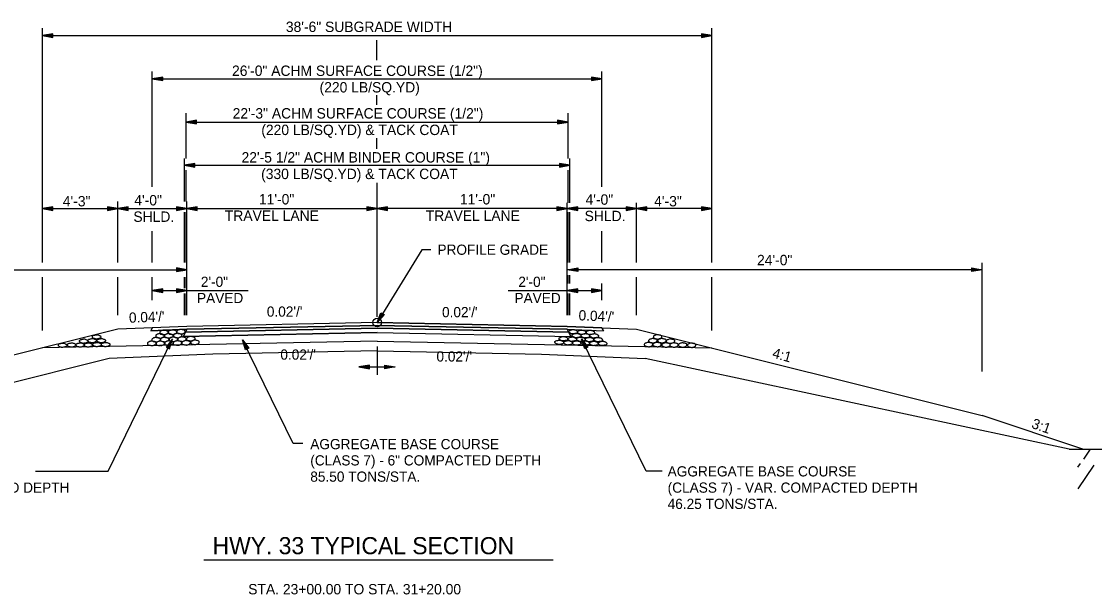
# Model space of a CAD drawing. Extents: x 1461846 to 1462006, y 1686171 to 1686805.
# Drawn here: x 1461905.5 to 1461967.5, y 1686172.9 to 1686206 of the extents above; entities that cross this region are included whole.
import ezdxf

# ---------------------------------------------------------------- set-up
doc = ezdxf.new("R2010")
doc.units = 0
for name, color, linetype in [('1', 7, 'Continuous'), ('10', 7, 'Continuous'), ('12', 7, 'Continuous'), ('19', 7, 'Continuous'), ('42', 7, 'Continuous'), ('Level 1', 7, 'Continuous'), ('Level 7', 7, 'Continuous'), ('Level 9', 7, 'Continuous')]:
    doc.layers.add(name, color=color, linetype=linetype)

# ---------------------------------------------------------------- blocks, each defined once
blk = doc.blocks.new('ROCKS')
at = {"layer": '1'}
blk.add_spline([(0.013, 0.06), (0.053, 0.053), (0.107, 0.033), (0.133, 0.013), (0.133, -0.007), (0.12, -0.033), (0.107, -0.04), (0.073, -0.053), (0.033, -0.067), (0.013, -0.067), (-0.02, -0.06), (-0.06, -0.053), (-0.087, -0.047), (-0.113, -0.02), (-0.113, -0.007), (-0.107, 0.02), (-0.087, 0.033), (-0.067, 0.047), (-0.033, 0.053), (-0.02, 0.06), (0.013, 0.06)], degree=3, dxfattribs=at)
blk = doc.blocks.new('4TO1 ABC')
at = {"layer": '1', "xscale": 0.1312491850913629, "yscale": 0.1312491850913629, "rotation": 180}
for p in [(0.00175, -0.00875), (-0.03325, -0.0385), (-0.016625, -0.023625), (0, -0.0385), (0.018375, -0.023625), (0.034125, -0.04025), (0.051625, -0.025375), (0.06475, -0.04025), (0.098, -0.04025), (0.133, -0.041125)]:
    blk.add_blockref('ROCKS', p, dxfattribs=at)

msp = doc.modelspace()

# ---------------------------------------------------------------- linework, layer by layer
at = {"layer": '10'}
msp.add_line((1461916.031, 1686174.906), (1461936.226, 1686174.906), dxfattribs=at)
at = {"layer": '19'}
for p, q in [((1461907.286, 1686205.314), (1461906.686, 1686205.209)), ((1461906.686, 1686205.209), (1461945.406, 1686205.209)), ((1461906.686, 1686205.209), (1461907.286, 1686205.104)), ((1461907.286, 1686205.259), (1461906.846, 1686205.224)), ((1461906.846, 1686205.194), (1461907.286, 1686205.154)), ((1461907.286, 1686205.104), (1461907.286, 1686205.314)), ((1461926.035, 1686203.793), (1461926.035, 1686204.941)), ((1461944.806, 1686205.314), (1461944.806, 1686205.104)), ((1461945.406, 1686205.209), (1461944.806, 1686205.314)), ((1461945.246, 1686205.224), (1461944.806, 1686205.259)), ((1461944.806, 1686205.104), (1461945.406, 1686205.209)), ((1461944.806, 1686205.154), (1461945.246, 1686205.194)), ((1461913.646, 1686202.814), (1461913.046, 1686202.709)), ((1461913.046, 1686202.709), (1461939.046, 1686202.709)), ((1461913.046, 1686202.709), (1461913.646, 1686202.604)), ((1461913.646, 1686202.759), (1461913.206, 1686202.724)), ((1461913.206, 1686202.694), (1461913.646, 1686202.654)), ((1461913.646, 1686202.604), (1461913.646, 1686202.814)), ((1461938.446, 1686202.814), (1461938.446, 1686202.604)), ((1461939.046, 1686202.709), (1461938.446, 1686202.814)), ((1461938.886, 1686202.724), (1461938.446, 1686202.759)), ((1461938.446, 1686202.604), (1461939.046, 1686202.709)), ((1461938.446, 1686202.654), (1461938.886, 1686202.694)), ((1461926.035, 1686201.209), (1461926.035, 1686201.758)), ((1461915.604, 1686200.314), (1461915.004, 1686200.209)), ((1461915.004, 1686200.209), (1461937.088, 1686200.209)), ((1461915.004, 1686200.209), (1461915.604, 1686200.104)), ((1461915.604, 1686200.259), (1461915.164, 1686200.224)), ((1461915.164, 1686200.194), (1461915.604, 1686200.154)), ((1461915.604, 1686200.104), (1461915.604, 1686200.314)), ((1461936.488, 1686200.314), (1461936.488, 1686200.104)), ((1461937.088, 1686200.209), (1461936.488, 1686200.314)), ((1461936.928, 1686200.224), (1461936.488, 1686200.259)), ((1461936.488, 1686200.104), (1461937.088, 1686200.209)), ((1461936.488, 1686200.154), (1461936.928, 1686200.194)), ((1461926.035, 1686198.657), (1461926.035, 1686199.284)), ((1461915.499, 1686197.814), (1461914.899, 1686197.709)), ((1461914.899, 1686197.709), (1461937.193, 1686197.709)), ((1461914.899, 1686197.709), (1461915.499, 1686197.604)), ((1461915.499, 1686197.759), (1461915.059, 1686197.724)), ((1461915.059, 1686197.694), (1461915.499, 1686197.654)), ((1461915.499, 1686197.604), (1461915.499, 1686197.814)), ((1461936.593, 1686197.814), (1461936.593, 1686197.604)), ((1461937.193, 1686197.709), (1461936.593, 1686197.814)), ((1461937.033, 1686197.724), (1461936.593, 1686197.759)), ((1461936.593, 1686197.604), (1461937.193, 1686197.709)), ((1461936.593, 1686197.654), (1461937.033, 1686197.694)), ((1461907.286, 1686195.314), (1461906.686, 1686195.209)), ((1461906.686, 1686195.209), (1461907.286, 1686195.104)), ((1461907.286, 1686195.259), (1461906.846, 1686195.224)), ((1461906.846, 1686195.194), (1461907.286, 1686195.154)), ((1461907.286, 1686195.104), (1461907.286, 1686195.314)), ((1461910.446, 1686195.314), (1461910.446, 1686195.104)), ((1461911.046, 1686195.209), (1461910.446, 1686195.314)), ((1461910.886, 1686195.224), (1461910.446, 1686195.259)), ((1461910.446, 1686195.104), (1461911.046, 1686195.209)), ((1461910.446, 1686195.154), (1461910.886, 1686195.194)), ((1461911.646, 1686195.314), (1461911.046, 1686195.209)), ((1461911.046, 1686195.209), (1461911.646, 1686195.104)), ((1461911.646, 1686195.259), (1461911.206, 1686195.224)), ((1461911.206, 1686195.194), (1461911.646, 1686195.154)), ((1461911.646, 1686195.104), (1461911.646, 1686195.314)), ((1461914.446, 1686195.314), (1461914.446, 1686195.104)), ((1461915.046, 1686195.209), (1461914.446, 1686195.314)), ((1461914.886, 1686195.224), (1461914.446, 1686195.259)), ((1461914.446, 1686195.104), (1461915.046, 1686195.209)), ((1461914.446, 1686195.154), (1461914.886, 1686195.194)), ((1461915.646, 1686195.314), (1461915.046, 1686195.209)), ((1461915.046, 1686195.209), (1461915.646, 1686195.104)), ((1461915.646, 1686195.259), (1461915.206, 1686195.224)), ((1461915.206, 1686195.194), (1461915.646, 1686195.154)), ((1461915.646, 1686195.104), (1461915.646, 1686195.314)), ((1461925.446, 1686195.314), (1461925.446, 1686195.104)), ((1461926.046, 1686195.209), (1461925.446, 1686195.314)), ((1461925.886, 1686195.224), (1461925.446, 1686195.259)), ((1461925.446, 1686195.104), (1461926.046, 1686195.209)), ((1461925.446, 1686195.154), (1461925.886, 1686195.194)), ((1461926.646, 1686195.314), (1461926.046, 1686195.209)), ((1461926.046, 1686195.209), (1461926.646, 1686195.104)), ((1461926.646, 1686195.259), (1461926.206, 1686195.224)), ((1461926.206, 1686195.194), (1461926.646, 1686195.154)), ((1461926.646, 1686195.104), (1461926.646, 1686195.314)), ((1461936.446, 1686195.314), (1461936.446, 1686195.104)), ((1461937.046, 1686195.209), (1461936.446, 1686195.314)), ((1461936.886, 1686195.224), (1461936.446, 1686195.259)), ((1461936.446, 1686195.104), (1461937.046, 1686195.209)), ((1461936.446, 1686195.154), (1461936.886, 1686195.194)), ((1461937.646, 1686195.314), (1461937.046, 1686195.209)), ((1461937.046, 1686195.209), (1461937.646, 1686195.104)), ((1461937.646, 1686195.259), (1461937.206, 1686195.224)), ((1461937.206, 1686195.194), (1461937.646, 1686195.154)), ((1461937.646, 1686195.104), (1461937.646, 1686195.314)), ((1461940.446, 1686195.314), (1461940.446, 1686195.104)), ((1461941.046, 1686195.209), (1461940.446, 1686195.314)), ((1461940.886, 1686195.224), (1461940.446, 1686195.259)), ((1461940.446, 1686195.104), (1461941.046, 1686195.209)), ((1461940.446, 1686195.154), (1461940.886, 1686195.194)), ((1461941.646, 1686195.314), (1461941.046, 1686195.209)), ((1461941.046, 1686195.209), (1461941.646, 1686195.104)), ((1461941.646, 1686195.259), (1461941.206, 1686195.224)), ((1461941.206, 1686195.194), (1461941.646, 1686195.154)), ((1461941.646, 1686195.104), (1461941.646, 1686195.314)), ((1461944.806, 1686195.314), (1461944.806, 1686195.104)), ((1461945.406, 1686195.209), (1461944.806, 1686195.314)), ((1461945.246, 1686195.224), (1461944.806, 1686195.259)), ((1461944.806, 1686195.104), (1461945.406, 1686195.209)), ((1461944.806, 1686195.154), (1461945.246, 1686195.194)), ((1461914.446, 1686191.774), (1461914.446, 1686191.564)), ((1461915.046, 1686191.669), (1461914.446, 1686191.774)), ((1461914.886, 1686191.684), (1461914.446, 1686191.719)), ((1461937.046, 1686191.669), (1461937.646, 1686191.774)), ((1461937.206, 1686191.684), (1461937.646, 1686191.719)), ((1461937.646, 1686191.774), (1461937.646, 1686191.564)), ((1461960.446, 1686191.564), (1461960.446, 1686191.774)), ((1461960.446, 1686191.774), (1461961.046, 1686191.669)), ((1461960.446, 1686191.719), (1461960.886, 1686191.684)), ((1461914.446, 1686191.564), (1461915.046, 1686191.669)), ((1461914.446, 1686191.614), (1461914.886, 1686191.654)), ((1461937.646, 1686191.564), (1461937.046, 1686191.669)), ((1461937.646, 1686191.614), (1461937.206, 1686191.654)), ((1461961.046, 1686191.669), (1461960.446, 1686191.564)), ((1461960.886, 1686191.654), (1461960.446, 1686191.614)), ((1461913.646, 1686190.574), (1461913.046, 1686190.469)), ((1461913.046, 1686190.469), (1461918.583, 1686190.469)), ((1461913.046, 1686190.469), (1461913.646, 1686190.364)), ((1461913.646, 1686190.519), (1461913.206, 1686190.484)), ((1461913.206, 1686190.454), (1461913.646, 1686190.414)), ((1461913.646, 1686190.364), (1461913.646, 1686190.574)), ((1461914.446, 1686190.574), (1461914.446, 1686190.364)), ((1461915.046, 1686190.469), (1461914.446, 1686190.574)), ((1461914.886, 1686190.484), (1461914.446, 1686190.519)), ((1461914.446, 1686190.364), (1461915.046, 1686190.469)), ((1461914.446, 1686190.414), (1461914.886, 1686190.454)), ((1461933.62, 1686190.469), (1461939.046, 1686190.469)), ((1461937.646, 1686190.574), (1461937.046, 1686190.469)), ((1461937.046, 1686190.469), (1461937.646, 1686190.364)), ((1461937.646, 1686190.519), (1461937.206, 1686190.484)), ((1461937.206, 1686190.454), (1461937.646, 1686190.414)), ((1461937.646, 1686190.364), (1461937.646, 1686190.574)), ((1461938.446, 1686190.574), (1461938.446, 1686190.364)), ((1461939.046, 1686190.469), (1461938.446, 1686190.574)), ((1461938.886, 1686190.484), (1461938.446, 1686190.519)), ((1461938.446, 1686190.364), (1461939.046, 1686190.469)), ((1461938.446, 1686190.414), (1461938.886, 1686190.454)), ((1461926.046, 1686188.619), (1461915.046, 1686188.399)), ((1461926.046, 1686188.619), (1461915.046, 1686188.399)), ((1461926.046, 1686188.619), (1461926.269, 1686189.186)), ((1461926.447, 1686189.076), (1461926.046, 1686188.619)), ((1461926.046, 1686188.619), (1461937.046, 1686188.399)), ((1461937.046, 1686188.399), (1461926.046, 1686188.619)), ((1461926.12, 1686188.76), (1461926.313, 1686189.154)), ((1461926.406, 1686189.098), (1461926.143, 1686188.749)), ((1461926.269, 1686189.186), (1461926.447, 1686189.076)), ((1461911.046, 1686188.239), (1461891.046, 1686183.237)), ((1461915.046, 1686188.399), (1461911.046, 1686188.239)), ((1461913.046, 1686188.319), (1461912.961, 1686188.149)), ((1461913.046, 1686188.319), (1461912.961, 1686188.149)), ((1461915.046, 1686188.233), (1461912.961, 1686188.149)), ((1461912.961, 1686188.149), (1461915.046, 1686188.233)), ((1461915.046, 1686188.399), (1461913.046, 1686188.319)), ((1461914.962, 1686188.064), (1461914.835, 1686187.812)), ((1461914.962, 1686188.064), (1461914.835, 1686187.812)), ((1461926.046, 1686188.036), (1461914.835, 1686187.812)), ((1461914.835, 1686187.812), (1461926.046, 1686188.036)), ((1461926.046, 1686188.286), (1461914.962, 1686188.064)), ((1461914.962, 1686188.064), (1461926.046, 1686188.286)), ((1461926.046, 1686188.286), (1461914.962, 1686188.064)), ((1461915.046, 1686188.233), (1461914.962, 1686188.064)), ((1461915.046, 1686188.233), (1461914.962, 1686188.064)), ((1461926.046, 1686188.453), (1461915.046, 1686188.233)), ((1461915.046, 1686188.233), (1461926.046, 1686188.453)), ((1461926.046, 1686188.453), (1461915.046, 1686188.233)), ((1461926.046, 1686188.453), (1461937.046, 1686188.233)), ((1461926.046, 1686188.453), (1461937.046, 1686188.233)), ((1461937.046, 1686188.233), (1461926.046, 1686188.453)), ((1461926.046, 1686188.286), (1461937.13, 1686188.064)), ((1461926.046, 1686188.286), (1461937.13, 1686188.064)), ((1461937.13, 1686188.064), (1461926.046, 1686188.286)), ((1461926.046, 1686188.036), (1461937.256, 1686187.812)), ((1461926.046, 1686188.036), (1461937.256, 1686187.812)), ((1461937.046, 1686188.399), (1461941.046, 1686188.239)), ((1461939.046, 1686188.319), (1461937.046, 1686188.399)), ((1461937.046, 1686188.233), (1461939.131, 1686188.149)), ((1461937.046, 1686188.233), (1461937.13, 1686188.064)), ((1461937.046, 1686188.233), (1461939.131, 1686188.149)), ((1461937.13, 1686188.064), (1461937.046, 1686188.233)), ((1461937.13, 1686188.064), (1461937.256, 1686187.812)), ((1461937.256, 1686187.812), (1461937.13, 1686188.064)), ((1461939.046, 1686188.319), (1461939.131, 1686188.149)), ((1461939.131, 1686188.149), (1461939.046, 1686188.319)), ((1461941.046, 1686188.239), (1461961.046, 1686183.237)), ((1461926.046, 1686187.536), (1461906.686, 1686187.149)), ((1461910.487, 1686180.024), (1461914.215, 1686187.683)), ((1461914.215, 1686187.683), (1461913.852, 1686187.194)), ((1461914.133, 1686187.546), (1461913.901, 1686187.173)), ((1461913.995, 1686187.124), (1461914.158, 1686187.533)), ((1461914.039, 1686187.101), (1461914.215, 1686187.683)), ((1461921.185, 1686181.617), (1461918.264, 1686187.618)), ((1461918.44, 1686187.037), (1461918.264, 1686187.618)), ((1461918.264, 1686187.618), (1461918.627, 1686187.13)), ((1461918.484, 1686187.06), (1461918.321, 1686187.469)), ((1461918.346, 1686187.482), (1461918.579, 1686187.109)), ((1461926.046, 1686187.536), (1461945.406, 1686187.149)), ((1461941.604, 1686180.024), (1461937.876, 1686187.683)), ((1461938.053, 1686187.101), (1461937.876, 1686187.683)), ((1461937.876, 1686187.683), (1461938.24, 1686187.194)), ((1461938.097, 1686187.124), (1461937.934, 1686187.533)), ((1461937.959, 1686187.546), (1461938.191, 1686187.173)), ((1461916.546, 1686186.787), (1461910.546, 1686186.547)), ((1461913.852, 1686187.194), (1461914.039, 1686187.101)), ((1461926.046, 1686186.977), (1461916.546, 1686186.787)), ((1461918.627, 1686187.13), (1461918.44, 1686187.037)), ((1461926.046, 1686186.977), (1461935.546, 1686186.787)), ((1461935.546, 1686186.787), (1461941.546, 1686186.547)), ((1461938.24, 1686187.194), (1461938.053, 1686187.101)), ((1461910.546, 1686186.547), (1461903.549, 1686184.797)), ((1461966.072, 1686181.3), (1461941.546, 1686186.547)), ((1461966.857, 1686181.3), (1461961.046, 1686183.237)), ((1461921.755, 1686181.617), (1461921.185, 1686181.617)), ((1461966.072, 1686181.3), (1461979.182, 1686181.3)), ((1461966.915, 1686180.717), (1461967.306, 1686181.3)), ((1461906.289, 1686180.024), (1461910.487, 1686180.024)), ((1461942.524, 1686180.024), (1461941.604, 1686180.024)), ((1461966.575, 1686180.249), (1461966.729, 1686180.475)), ((1461966.597, 1686179), (1461967.524, 1686180.383))]:
    msp.add_line(p, q, dxfattribs=at)
msp.add_lwpolyline([(1461929.146, 1686192.818), (1461928.629, 1686192.818), (1461926.046, 1686188.619)], dxfattribs=at)
msp.add_circle((1461926.051, 1686188.617), 0.25, dxfattribs=at)
at = {"layer": '42'}
for p, q in [((1461926.046, 1686187.234), (1461926.046, 1686185.602)), ((1461925.598, 1686186.159), (1461924.998, 1686186.054)), ((1461925.598, 1686186.104), (1461925.158, 1686186.069)), ((1461925.598, 1686185.949), (1461925.598, 1686186.159)), ((1461926.493, 1686185.949), (1461926.493, 1686186.159)), ((1461926.493, 1686186.159), (1461927.093, 1686186.054)), ((1461926.493, 1686186.104), (1461926.933, 1686186.069)), ((1461924.998, 1686186.054), (1461925.598, 1686185.949)), ((1461924.998, 1686186.054), (1461927.093, 1686186.054)), ((1461925.158, 1686186.039), (1461925.598, 1686185.999)), ((1461927.093, 1686186.054), (1461926.493, 1686185.949)), ((1461926.933, 1686186.039), (1461926.493, 1686185.999))]:
    msp.add_line(p, q, dxfattribs=at)
at = {"layer": 'Level 7'}
msp.add_line((1461926.046, 1686188.94), (1461926.046, 1686196.705), dxfattribs=at)
at = {"layer": 'Level 9'}
for p, q in [((1461906.686, 1686192.097), (1461906.686, 1686205.636)), ((1461945.406, 1686192.097), (1461945.406, 1686205.636)), ((1461913.046, 1686196.466), (1461913.046, 1686203.136)), ((1461939.046, 1686196.466), (1461939.046, 1686203.136)), ((1461915.004, 1686198.098), (1461915.004, 1686200.715)), ((1461937.088, 1686198.098), (1461937.088, 1686200.715)), ((1461914.899, 1686195.612), (1461914.899, 1686198.098)), ((1461937.193, 1686195.541), (1461937.193, 1686198.098)), ((1461915.004, 1686195.612), (1461915.004, 1686197.427)), ((1461937.088, 1686195.541), (1461937.088, 1686197.427)), ((1461911.046, 1686192.097), (1461911.046, 1686195.612)), ((1461915.046, 1686189.045), (1461915.046, 1686195.612)), ((1461937.046, 1686189.045), (1461937.046, 1686195.541)), ((1461941.046, 1686192.097), (1461941.046, 1686195.541)), ((1461906.686, 1686195.209), (1461915.046, 1686195.209)), ((1461914.899, 1686192.097), (1461914.899, 1686194.994)), ((1461915.004, 1686192.097), (1461915.004, 1686194.994)), ((1461915.046, 1686195.209), (1461926.046, 1686195.209)), ((1461937.046, 1686195.209), (1461926.046, 1686195.209)), ((1461945.406, 1686195.209), (1461937.046, 1686195.209)), ((1461937.088, 1686192.097), (1461937.088, 1686194.994)), ((1461937.193, 1686192.097), (1461937.193, 1686194.994)), ((1461913.046, 1686192.097), (1461913.046, 1686193.911)), ((1461939.046, 1686192.097), (1461939.046, 1686193.911)), ((1461961.046, 1686185.782), (1461961.046, 1686192.072)), ((1461891.046, 1686191.669), (1461915.046, 1686191.669)), ((1461906.686, 1686188.154), (1461906.686, 1686191.237)), ((1461911.046, 1686189.045), (1461911.046, 1686191.237)), ((1461913.046, 1686189.904), (1461913.046, 1686191.237)), ((1461914.899, 1686190.614), (1461914.899, 1686191.237)), ((1461915.004, 1686190.614), (1461915.004, 1686191.237)), ((1461961.046, 1686191.669), (1461937.046, 1686191.669)), ((1461937.088, 1686190.879), (1461937.088, 1686191.351)), ((1461937.193, 1686190.879), (1461937.193, 1686191.351)), ((1461941.046, 1686189.045), (1461941.046, 1686191.237)), ((1461945.406, 1686188.154), (1461945.406, 1686191.237)), ((1461939.046, 1686189.904), (1461939.046, 1686190.879)), ((1461914.899, 1686189.045), (1461914.899, 1686190.306)), ((1461915.004, 1686189.045), (1461915.004, 1686190.306)), ((1461937.088, 1686189.045), (1461937.088, 1686190.306)), ((1461937.193, 1686189.045), (1461937.193, 1686190.306))]:
    msp.add_line(p, q, dxfattribs=at)

# ---------------------------------------------------------------- block references
at = {"layer": '19', "xscale": 14.999970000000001, "yscale": -14.999970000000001, "rotation": 180}
msp.add_blockref('4TO1 ABC', (1461909.83, 1686187.917), dxfattribs=at)
at = {"layer": '19', "xscale": 14.999970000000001, "yscale": 14.999970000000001}
msp.add_blockref('4TO1 ABC', (1461942.261, 1686187.917), dxfattribs=at)
at = {"layer": 'Level 1', "xscale": 2.011654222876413}
for p, yscale, rotation in [((1461913.469, 1686187.856), 2.011654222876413, 1.8263814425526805), ((1461913.7, 1686188.053), 2.011654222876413, 1.8263814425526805), ((1461913.985, 1686187.86), 2.011654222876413, 1.8263814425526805), ((1461914.187, 1686188.062), 2.011654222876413, 1.8263814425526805), ((1461914.494, 1686187.873), 2.011654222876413, 1.8263814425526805), ((1461914.685, 1686188.095), 2.011654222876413, 1.8263814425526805), ((1461937.407, 1686188.095), -2.011654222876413, 178.17361855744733), ((1461937.597, 1686187.873), -2.011654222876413, 178.17361855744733), ((1461937.905, 1686188.062), -2.011654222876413, 178.17361855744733), ((1461938.107, 1686187.86), -2.011654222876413, 178.17361855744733), ((1461938.392, 1686188.053), -2.011654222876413, 178.17361855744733), ((1461938.622, 1686187.856), -2.011654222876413, 178.17361855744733), ((1461912.993, 1686187.421), 2.011654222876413, 1.8263814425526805), ((1461913.245, 1686187.638), 2.011654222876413, 1.8263814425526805), ((1461913.489, 1686187.417), 2.011654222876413, 1.8263814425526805), ((1461913.743, 1686187.641), 2.011654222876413, 1.8263814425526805), ((1461913.992, 1686187.436), 2.011654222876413, 1.8263814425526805), ((1461914.239, 1686187.657), 2.011654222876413, 1.8263814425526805), ((1461914.483, 1686187.44), 2.011654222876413, 1.8263814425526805), ((1461914.744, 1686187.665), 2.011654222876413, 1.8263814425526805), ((1461914.984, 1686187.455), 2.011654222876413, 1.8263814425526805), ((1461915.25, 1686187.69), 2.011654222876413, 1.8263814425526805), ((1461915.491, 1686187.48), 2.011654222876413, 1.8263814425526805), ((1461936.601, 1686187.48), -2.011654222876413, 178.17361855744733), ((1461936.842, 1686187.69), -2.011654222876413, 178.17361855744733), ((1461937.108, 1686187.455), -2.011654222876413, 178.17361855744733), ((1461937.348, 1686187.665), -2.011654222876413, 178.17361855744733), ((1461937.609, 1686187.44), -2.011654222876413, 178.17361855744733), ((1461937.853, 1686187.657), -2.011654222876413, 178.17361855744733), ((1461938.099, 1686187.436), -2.011654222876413, 178.17361855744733), ((1461938.349, 1686187.641), -2.011654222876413, 178.17361855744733), ((1461938.602, 1686187.417), -2.011654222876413, 178.17361855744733), ((1461938.847, 1686187.638), -2.011654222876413, 178.17361855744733), ((1461939.099, 1686187.421), -2.011654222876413, 178.17361855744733)]:
    msp.add_blockref('ROCKS', p, dxfattribs=dict(at, yscale=yscale, rotation=rotation))

# ---------------------------------------------------------------- texts
at = {"layer": '10'}
msp.add_text('STA. 23+00.00 TO STA. 31+20.00', height=0.6, rotation=359.99538, dxfattribs=at).set_placement((1461918.592, 1686172.904))
at = {"layer": '12'}
msp.add_text('HWY. 33 TYPICAL SECTION', height=0.98999, rotation=359.99538, dxfattribs=at).set_placement((1461916.532, 1686175.226))
at = {"layer": '19'}
for s, height, rotation, p in [('4\'-3"', 0.6, 360, (1461907.871, 1686195.335)), ('PROFILE GRADE', 0.59001, 360, (1461929.537, 1686192.535)), ('2\'-0"', 0.59, 360, (1461915.854, 1686190.68)), ('PAVED', 0.59, 360, (1461915.631, 1686189.74)), ("0.04'/'", 0.59, 2.16019, (1461911.706, 1686188.605)), ("0.02'/'", 0.59, 360, (1461919.669, 1686188.959)), ("0.02'/'", 0.59, 360, (1461919.669, 1686188.959)), ("0.02'/'", 0.59, 360, (1461929.801, 1686188.928)), ("0.02'/'", 0.59, 360, (1461929.801, 1686188.928)), ("0.04'/'", 0.59, 357.38867, (1461937.687, 1686188.752)), ("0.02'/'", 0.59, 360, (1461920.451, 1686186.472)), ("0.02'/'", 0.59, 360, (1461929.479, 1686186.365)), ('4:1', 0.59, 344.53267, (1461948.863, 1686186.6)), ('3:1', 0.59, 340.49426, (1461963.849, 1686182.541)), ('AGGREGATE BASE COURSE', 0.59001, 360, (1461922.182, 1686181.296)), ('(CLASS 7) - 6" COMPACTED DEPTH', 0.59001, 360, (1461922.182, 1686180.356)), ('85.50 TONS/STA.', 0.59001, 360, (1461922.182, 1686179.416)), ('(CLASS 7) - VAR. COMPACTED DEPTH', 0.59001, 360, (1461893.785, 1686178.781))]:
    msp.add_text(s, height=height, rotation=rotation, dxfattribs=at).set_placement(p)
for s, height, p in [('4\'-3"', 0.6, (1461942.071, 1686195.335)), ('2\'-0"', 0.59, (1461934.214, 1686190.68)), ('PAVED', 0.59, (1461933.991, 1686189.74)), ('AGGREGATE BASE COURSE', 0.59001, (1461942.85, 1686179.721)), ('(CLASS 7) - VAR. COMPACTED DEPTH', 0.59001, (1461942.85, 1686178.781)), ('46.25 TONS/STA.', 0.59001, (1461942.85, 1686177.841))]:
    msp.add_text(s, height=height, dxfattribs=at).set_placement(p)
at = {"layer": '42'}
for s, height, p in [('38\'-6" SUBGRADE WIDTH', 0.60001, (1461920.769, 1686205.417)), ('26\'-0" ACHM SURFACE COURSE (1/2")', 0.60001, (1461917.656, 1686202.878)), ('(220 LB/SQ.YD)', 0.60001, (1461922.72, 1686201.922)), ('22\'-3" ACHM SURFACE COURSE (1/2")', 0.60001, (1461917.693, 1686200.415)), ('(220 LB/SQ.YD) & TACK COAT', 0.60001, (1461919.349, 1686199.459)), ('22\'-5 1/2" ACHM BINDER COURSE (1")', 0.60001, (1461918.207, 1686197.87)), ('(330 LB/SQ.YD) & TACK COAT', 0.60001, (1461919.339, 1686196.914)), ('11\'-0"', 0.6, (1461919.213, 1686195.448)), ('11\'-0"', 0.6, (1461930.833, 1686195.448)), ('4\'-0"', 0.6, (1461938.101, 1686195.431)), ('4\'-0"', 0.6, (1461912.005, 1686195.391)), ('SHLD.', 0.6, (1461911.951, 1686194.441)), ('TRAVEL LANE', 0.6, (1461917.24, 1686194.498)), ('TRAVEL LANE', 0.6, (1461928.861, 1686194.498)), ('SHLD.', 0.6, (1461938.047, 1686194.481))]:
    msp.add_text(s, height=height, rotation=360, dxfattribs=at).set_placement(p)
msp.add_text('24\'-0"', height=0.6, dxfattribs=at).set_placement((1461948.018, 1686191.933))

doc.saveas('drawing.dxf')
